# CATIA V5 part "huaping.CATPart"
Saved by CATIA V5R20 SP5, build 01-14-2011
Part number: 花瓶
Material "Light Green": density 7860 kg/m3, Young's modulus 2e+11 Pa, Poisson ratio 0.266
Material "Multicoloured Flag"
Material "Dark Green": density 7860 kg/m3, Young's modulus 2e+11 Pa, Poisson ratio 0.266
Material "China Blue": density 7860 kg/m3, Young's modulus 2e+11 Pa, Poisson ratio 0.266
Material "Ground Camouflage": density 7860 kg/m3, Young's modulus 2e+11 Pa, Poisson ratio 0.266
Material "Slightly Cloudy"
Material "Crisp Green": density 7860 kg/m3, Young's modulus 2e+11 Pa, Poisson ratio 0.266
Material "DS Light Blue": density 7860 kg/m3, Young's modulus 2e+11 Pa, Poisson ratio 0.266
Bounding box of the stored display mesh (mm): x -34.997 to 34.997, y -40.202 to 34.961, z -0.537 to 153.496
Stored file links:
  E:\180122235\huaping.CATPart
  C:\Program Files\Dassault Systemes\B20\intel_a\startup\materials\Catalog.CATMaterial
  C:\Program Files\Dassault Systemes\B20\intel_a\startup\materials\chessboard.jpg
  C:\Program Files\Dassault Systemes\B20\intel_a\startup\materials\DS_star.jpg
  C:\Program Files\Dassault Systemes\B20\intel_a\startup\materials\red_env_512x512.jpg
  C:\Program Files\Dassault Systemes\B20\intel_a\startup\materials\walnut.jpg
  C:\Program Files\Dassault Systemes\B20\intel_a\startup\materials\yellow_env_512x512.jpg
  C:\Program Files\Dassault Systemes\B20\intel_a\startup\materials\red_wood.jpg
  C:\Program Files\Dassault Systemes\B20\intel_a\startup\materials\blue_env_512x512.jpg
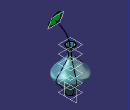
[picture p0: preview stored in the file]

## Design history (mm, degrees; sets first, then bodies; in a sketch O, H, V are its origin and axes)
Body1 (main body), material "DS Light Blue"
  Plane1: type Offset, RefPlane xy-plane, Offset 20
  Plane2: type Offset, RefPlane Plane1, Offset 20
  Plane3: type Offset, RefPlane Plane2, Offset 20
  Plane4: type Offset, RefPlane Plane3, Offset 20
  Plane5: type Offset, RefPlane Plane4, Offset 20
  Sketch1 on xy-plane, origin (0, 0, 0), H (1, 0, 0), V (0, 1, 0)
    circle A1 centre (0, 0) radius 10
  Sketch2 on Plane1, origin (0, 0, 20), H (1, 0, 0), V (0, 1, 0)
    circle A1 centre (0, 0) radius 20
  Sketch3 on Plane2, origin (0, 0, 40), H (1, 0, 0), V (0, 1, 0)
    circle A1 centre (0, 0) radius 35
  Sketch4 on Plane3, origin (0, 0, 60), H (1, 0, 0), V (0, 1, 0)
    circle A1 centre (0, 0) radius 20
  Sketch5 on Plane4, origin (0, 0, 80), H (1, 0, 0), V (0, 1, 0)
    circle A1 centre (0, 0) radius 5
  Sketch6 on Plane5, origin (0, 0, 100), H (1, 0, 0), V (0, 1, 0)
    circle A1 centre (0, 0) radius 10
  Loft1: solid, Sections (Sketch1; Sketch2; Sketch3; Sketch4; Sketch5; Sketch6)
  Shell1: ExtOffset 0, Face face of Loft1, IntOffset 1
  Sketch7 on yz-plane, origin (0, 0, 0), H (0, 1, 0), V (0, 0, 1)
    axis line L1 (0, 0) -> (0, 29.7212)
    line L2 (0, 0) -> (0, 20.1202)
    line L3 (0, 20.1202) -> (16.3337, 20.1202)
    line L4 (16.3337, 20.1202) -> (9.3439, 2.1572)
    line L5 (9.3439, 2.1572) -> (0, 1.2281)
    point P5 (0, 1.2281)
    line L6 (0, 1.2281) -> (0, 2.1572)
    vertical: L1 V, L2 V, L6 V
    horizontal: L3 H
    coincidence: P5 L1
Body2, material "Light Green"
  Sketch8 on yz-plane, origin (0, 0, 0), H (0, 1, 0), V (0, 0, 1)
    axis line L1 (0, 0) -> (0, 30.1857)
    line L2 (0, 0) -> (0, 19.0363)
    line L3 (0, 19.0363) -> (15.2464, 19.0363)
    line L4 (15.2464, 19.0363) -> (9.1886, 0)
    point P4 (9.1886, 0)
    line L5 (9.1886, 0) -> (0, 0)
    vertical: L1 V, L2 V
    horizontal: L3 H, L5 H
    coincidence: P4 H
  Shaft1: profile Sketch8, axis Sketch8.L1, angle 360
Body3, material "Dark Green"
Body4, material "Multicoloured Flag"
Body5, material "China Blue"
  Sketch9 on yz-plane, origin (0, 0, 0), H (0, 1, 0), V (0, 0, 1)
    spline S1 through (2.4455, 0) (-2.1193, 60.2837) (-0.9285, 102.0326) (-35.2633, 133.2948)
    point P1 (2.4455, 0)
    coincidence: P1 H
  Plane6: type Normal, Curve Sketch9, RefPoint vertex of Sketch9
  Sketch10 on Plane6, origin (0, -72.4934, 24.8988), H (1, 0, 0), V (0, 0.3248, 0.9458)
    circle A1 centre (0, 113.78) radius 0.63
    point P1 (0, 113.78)
    coincidence: P1 V
  Rib1: profile Sketch10, centre curve Sketch9
Body6, material "Crisp Green"
  Sketch11 on Plane6, origin (0, -72.4934, 24.8988), H (1, 0, 0), V (0, 0.3248, 0.9458)
    spline S1 through (-10.5028, 114.4599) (2.4929, 135.1086) (14.8795, 110.4111) (-1.5682, 102.516) (-10.5028, 114.4599)
    point P1 (-10.5028, 114.4599)
    point P2 (-10.5028, 114.4599)
    coincidence: P1 P2
  Pad1: profile Sketch11, direction (0, -0.9458, 0.3248), length 1
Body7
Body8, material "Ground Camouflage"
Body9, material "Slightly Cloudy"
